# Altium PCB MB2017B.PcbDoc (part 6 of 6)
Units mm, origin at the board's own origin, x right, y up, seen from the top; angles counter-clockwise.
Board outline 148.19 x 169.19 mm, 4 copper layers (Top Layer, Mid Layer 1, Mid Layer 2, Bottom Layer), stack 1.498 mm thick; 458 components, 208 nets, 1223 pads, 6162 vias.
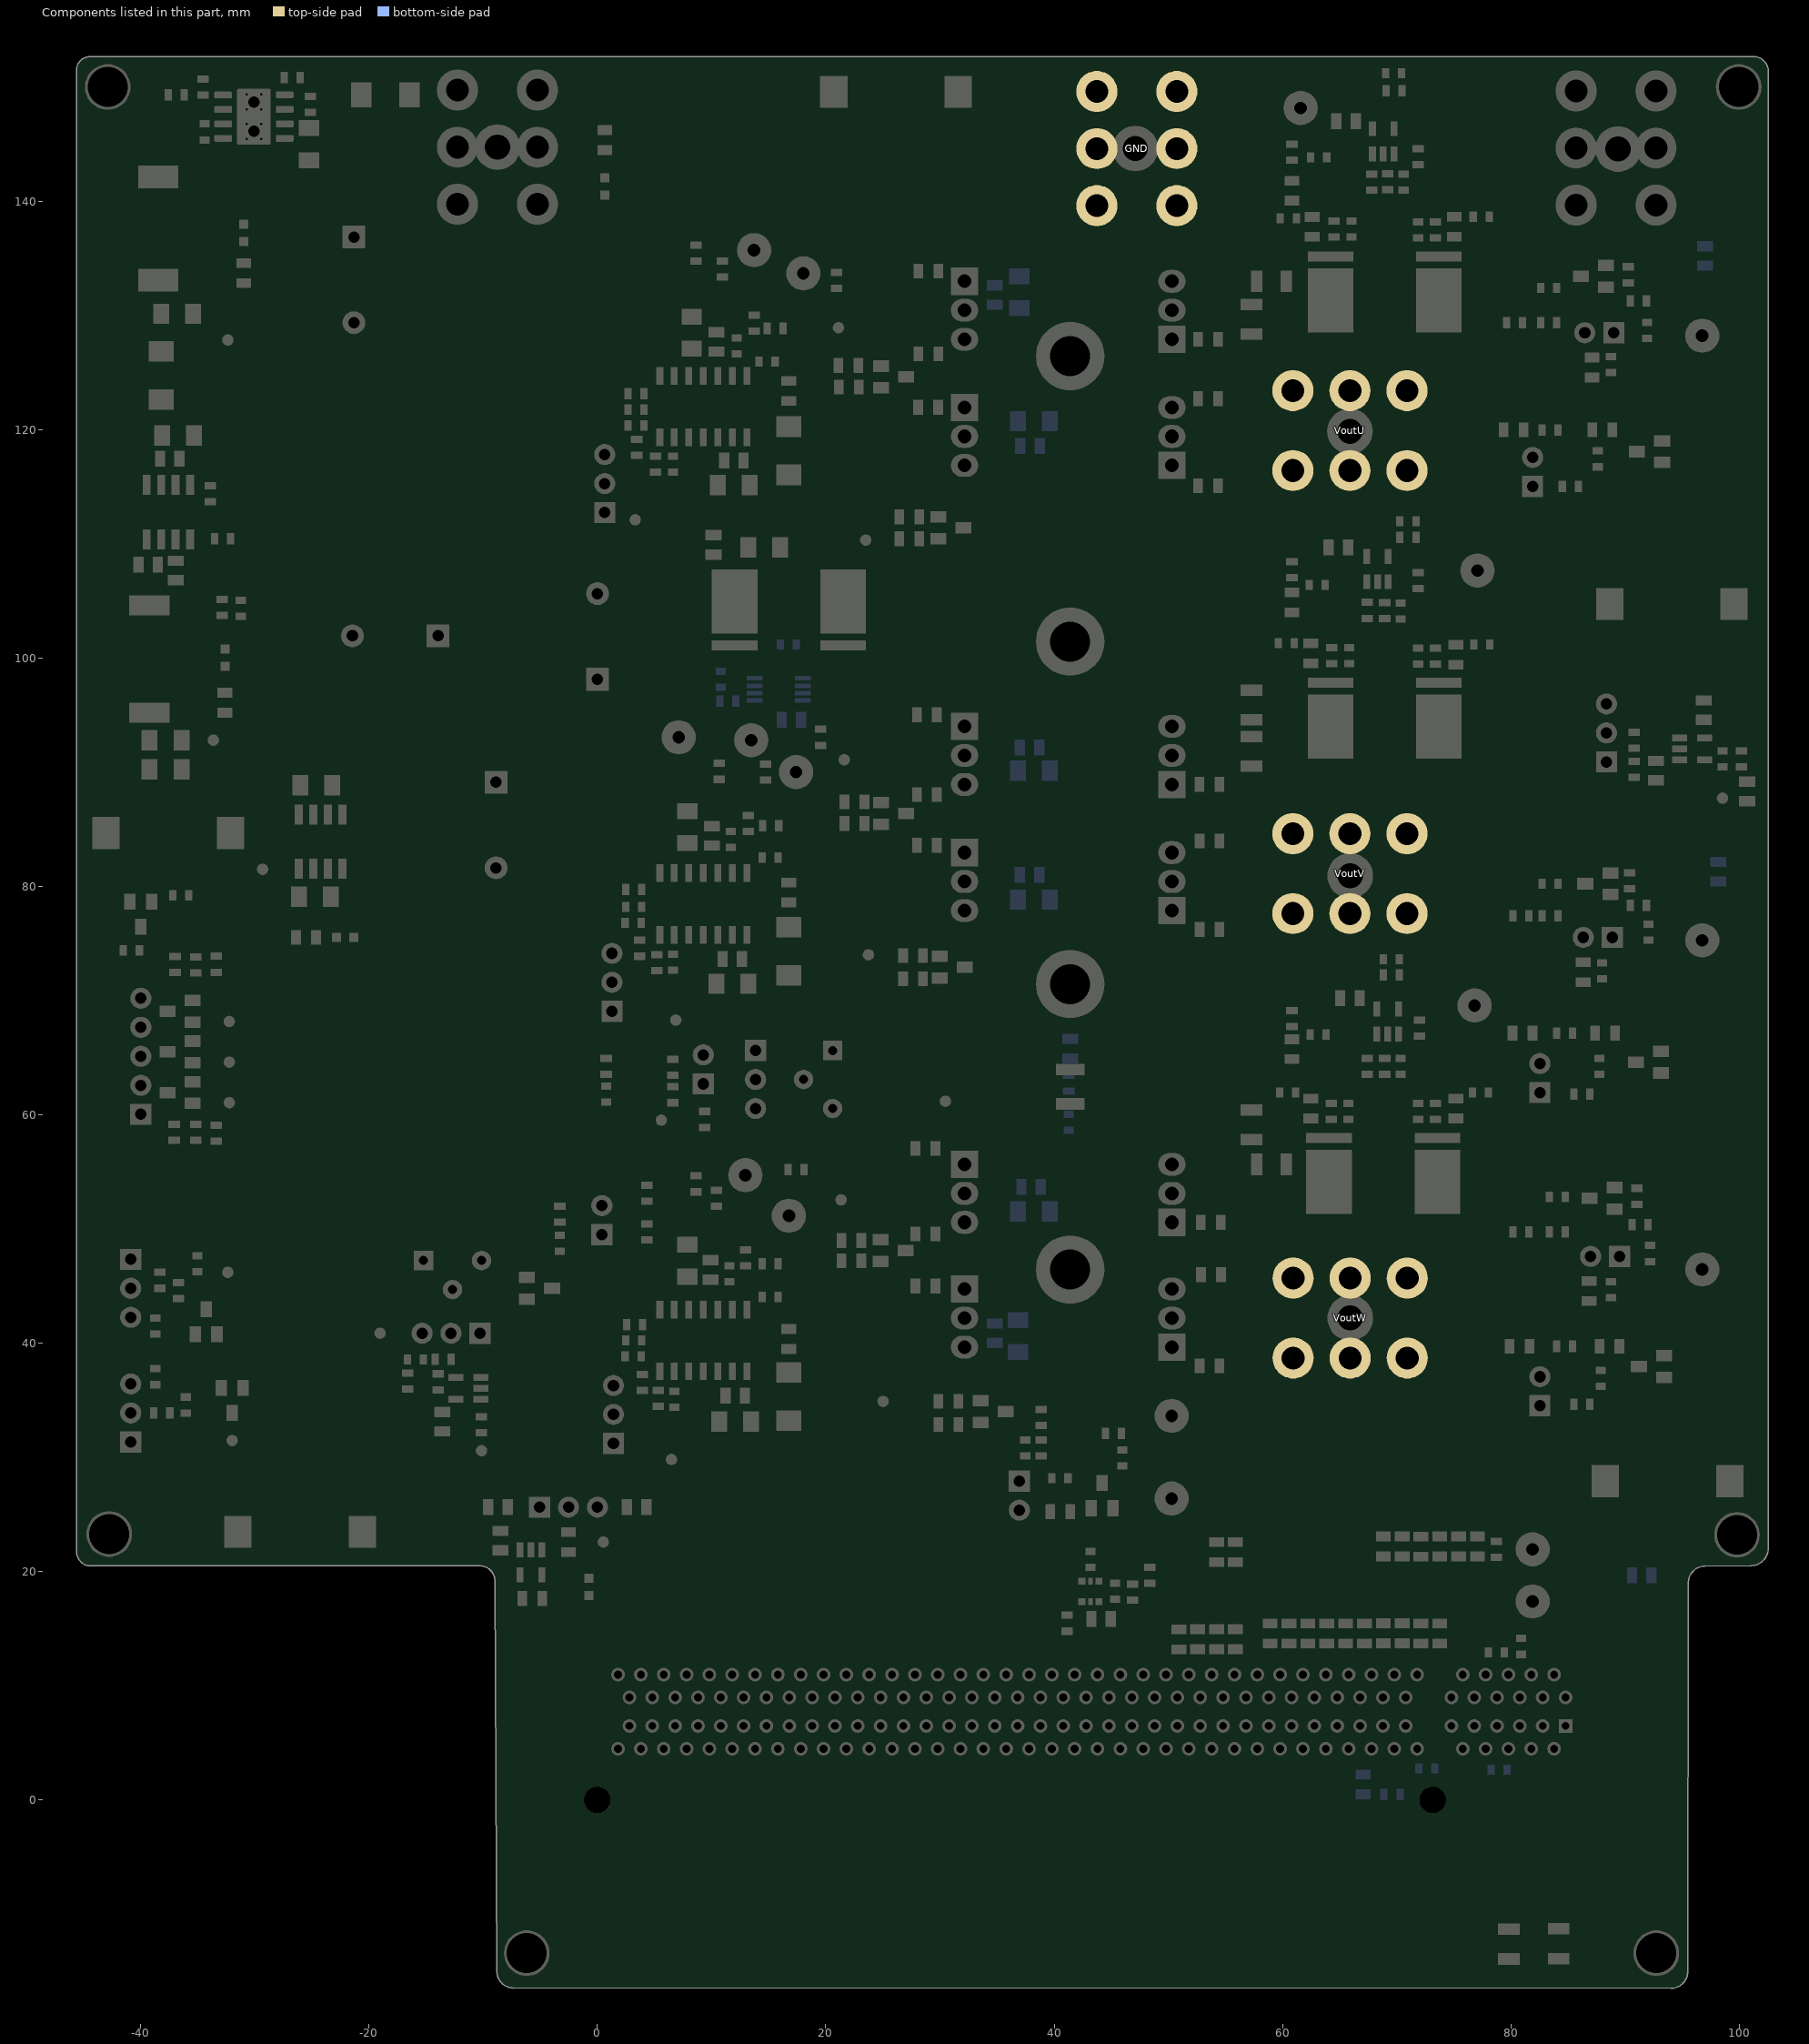
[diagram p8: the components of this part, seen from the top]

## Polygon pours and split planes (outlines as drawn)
GND on Mid Layer 1 "GND_L02_P015" (solid, remove dead copper, pour order 15): -44.577,152.4 100.838,152.4 102.108,151.13 102.108,21.844 101.219,20.955 96.012,20.955 95.123,20.066 95.123,-14.986 94.107,-16.002 -7.366,-16.002 -8.509,-14.859 -8.509,19.939 -9.525,20.955 -44.45,20.955 -45.339,21.844 -45.339,151.638
VoutW on Mid Layer 1 "VOUTW_L02_P002" (solid, pour order 2): 31.954,51.59 34.621,51.59 37.161,54.13 50.369,54.13 50.369,52.225 48.591,52.225 48.591,43.081 50.496,43.081 50.496,41.176 37.542,41.176 35.002,38.636 31.827,38.636 31.827,40.541 34.113,40.541 34.113,49.812 31.954,49.812
VoutU on Mid Layer 1 "VOUTU_L02_P000" (solid, pour order 0): 32.004,128.905 34.671,128.905 37.211,131.445 50.419,131.445 50.419,129.54 48.641,129.54 48.641,120.396 50.546,120.396 50.546,118.491 37.592,118.491 35.052,115.951 31.877,115.951 31.877,117.856 34.163,117.856 34.163,127.127 32.004,127.127
VoutV on Mid Layer 1 "VOUTV_L02_P001" (solid, pour order 1): 31.954,89.944 34.621,89.944 37.161,92.484 50.369,92.484 50.369,90.579 48.591,90.579 48.591,81.435 50.496,81.435 50.496,79.53 37.542,79.53 35.002,76.99 31.827,76.99 31.827,78.895 34.113,78.895 34.113,88.166 31.954,88.166
GND on Mid Layer 2 "GND_L03_P016" (solid, remove dead copper, pour order 16): -44.605,152.407 100.81,152.407 102.08,151.137 102.08,21.851 101.191,20.962 95.984,20.962 95.095,20.073 95.095,-14.979 94.079,-15.995 -7.394,-15.995 -8.537,-14.852 -8.537,19.946 -9.553,20.962 -44.478,20.962 -45.367,21.851 -45.367,151.645
VoutW on Mid Layer 2 "VOUTW_L03_P006" (solid, pour order 6): 32.004,51.562 34.671,51.562 37.211,54.102 50.419,54.102 50.419,52.197 48.641,52.197 48.641,43.053 50.546,43.053 50.546,41.148 37.592,41.148 35.052,38.608 31.877,38.608 31.877,40.513 34.163,40.513 34.163,49.784 32.004,49.784
VoutU on Mid Layer 2 "VOUTU_L03_P003" (solid, pour order 3): 32.004,128.905 34.671,128.905 37.211,131.445 50.419,131.445 50.419,129.54 48.641,129.54 48.641,120.396 50.546,120.396 50.546,118.491 37.592,118.491 35.052,115.951 31.877,115.951 31.877,117.856 34.163,117.856 34.163,127.127 32.004,127.127
VoutV on Mid Layer 2 "VOUTV_L03_P005" (solid, pour order 5): 32.004,89.916 34.671,89.916 37.211,92.456 50.419,92.456 50.419,90.551 48.641,90.551 48.641,81.407 50.546,81.407 50.546,79.502 37.592,79.502 35.052,76.962 31.877,76.962 31.877,78.867 34.163,78.867 34.163,88.138 32.004,88.138
GND on Bottom Layer "GND_L04_P017" (solid, remove dead copper, pour order 17): -44.577,152.4 100.838,152.4 102.108,151.13 102.108,21.844 101.219,20.955 96.012,20.955 95.123,20.066 95.123,-14.986 94.107,-16.002 -7.366,-16.002 -8.509,-14.859 -8.509,19.939 -9.525,20.955 -44.45,20.955 -45.339,21.844 -45.339,151.638
GND on Top Layer "GND_L01_P014" (solid, remove dead copper, pour order 14): -44.577,152.4 100.838,152.4 102.108,151.13 102.108,21.844 101.219,20.955 96.012,20.955 95.123,20.066 95.123,-14.986 94.107,-16.002 -7.366,-16.002 -8.509,-14.859 -8.509,19.939 -9.525,20.955 -44.45,20.955 -45.339,21.844 -45.339,151.638

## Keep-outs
Keep-Out Layer:
  circle w0.254: c-0.002,0 r1.351
  circle w0.254: c73.15,0 r1.351
  lines w0.3: 0.053,-13.927 0.053,-11.514 9.07,-11.514 9.07,-13.927 0.053,-13.927

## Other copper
Top Layer:
  rectangle net GND: 71.247,127.889 76.454,134.112
  rectangle net GND: 70.866,90.551 76.073,96.774
  rectangle net GND: 70.866,50.8 76.073,57.023
  region net VoutW: 72.931,36.235 72.931,47.665 58.961,47.665 58.961,36.235
  region net VoutV: 72.931,75.478 72.931,86.908 58.961,86.908 58.961,75.478
  region net VoutU: 72.898,114.173 72.898,125.603 58.928,125.603 58.928,114.173
  rectangle net GND: 70.612,129.921 77.851,132.715
  rectangle net GND: 70.739,92.583 77.978,95.377
  rectangle net GND: 70.231,52.705 77.47,55.499
  rectangle net OC_Bias: 6.477,73.914 6.985,76.073
  rectangle net NetQ18_1: 28.321,73.533 30.48,74.422
  rectangle net NetQ10_1: 22.987,48.641 25.146,49.403
  rectangle net NetC64_2: 3.683,40.005 4.064,41.783
  rectangle net OC_Bias: 6.477,35.814 6.985,37.592
  rectangle net OC_Bias: 6.477,117.475 6.985,119.507
  rectangle net GND: 43.688,17.018 45.72,17.653
  rectangle net W: 55.731,56.17 58.271,58.456
  rectangle net U: 55.753,130.429 58.293,132.715
  rectangle net V: 52.451,92.583 58.293,95.123
  rectangle net NetJ2_1: 55.722,96.647 58.262,128.905
  rectangle net NetJ3_2: 55.753,59.944 58.293,91.059
  rectangle net Vcc_power: 20.447,102.362 34.671,107.95
  rectangle net Vbat: 9.398,107.569 13.97,109.601
  rectangle net Vbat: 2.794,102.362 13.97,107.95
  rectangle net Vbat: 0.762,96.012 8.255,103.251
  rectangle net Vbat: -15.367,87.884 1.397,103.251
  rectangle net NetC2_1: -21.59,135.89 -20.32,150.368
  rectangle net NetC1_1: -34.671,144.907 -32.131,145.796
  rectangle net GND: 83.477,137.604 94.907,152.019
  rectangle net GND: 41.402,137.287 52.832,151.765
  rectangle net Vbat: -14.478,100.711 -3.048,151.765
  region net NetJ1_1: 59.817,56.642 66.167,56.642 66.167,51.181 62.103,51.181 62.103,54.737 59.817,54.737
  region net V: 56.388,95.123 59.944,95.123 59.944,96.647 66.167,96.647 66.167,91.059 59.944,91.059 59.944,92.583 56.388,92.583
  region net NetJ4_1: 59.817,133.985 66.294,133.985 66.294,128.397 62.23,128.397 62.23,132.08 59.817,132.08
  region net W: 45.466,56.696 45.466,43.688 50.641,43.688 50.641,45.72 48.609,45.72 48.609,54.737 58.261,54.737 58.261,56.696
  region net V: 45.466,94.996 45.466,82.042 50.673,82.042 50.673,83.947 48.641,83.947 48.641,93.091 58.293,93.091 58.293,94.996
  region net U: 45.466,133.985 45.466,121.031 50.673,121.031 50.673,122.936 48.641,122.936 48.641,132.08 58.293,132.08 58.293,133.985
  region net Vcc_power: 35.231,107.182 31.421,107.182 35.231,110.992
  region net Vcc_power: 34.677,103.684 34.677,99.874 30.867,103.684
  region net Vbat: 6.679,103.003 10.489,103.003 6.679,99.193
  region net Vcc_power: 31.75,131.445 37.465,131.445 37.465,41.275 31.877,41.275 31.877,43.18 34.163,43.18 34.163,52.197 31.877,52.197 31.877,54.102 32.004,53.975 34.163,53.975 34.163,79.502 31.877,79.502 31.877,81.407 34.163,81.407 34.163,90.551 31.877,90.551 31.877,92.456 34.163,92.456 34.163,118.491 31.877,118.491 31.877,120.396 34.163,120.396 34.163,129.54 31.75,129.54
  region net Vbat: 3.81,102.616 0,102.616 3.81,106.426
  region net Vbat: -3.81,102.362 -3.81,106.172 0,102.362
  region net Vbat: 1.143,96.139 4.953,96.139 1.143,92.329
  text "1" at 0.942,-13.292 h1.8
Mid Layer 1:
  rectangle net GND: 83.312,137.541 95.377,151.892
  rectangle net GND: 41.402,137.414 53.467,151.765
  rectangle net Epad: -33.147,144.78 -26.797,150.114
  rectangle net VoutU: 57.476,117.324 59.381,121.896
  rectangle net VoutV: 57.531,78.232 59.436,82.804
  rectangle net VoutW: 57.785,39.878 59.69,44.45
  rectangle net VoutW: 50.291,41.322 60.324,43.227
  rectangle net VoutV: 50.418,79.549 60.451,81.454
  rectangle net VoutU: 50.038,118.491 60.071,120.396
  region net VoutW: 73.082,36.514 73.082,47.944 59.112,47.944 59.112,36.514
  region net VoutV: 72.955,75.249 72.955,86.679 58.985,86.679 58.985,75.249
  region net VoutU: 72.898,114.046 72.898,125.476 58.928,125.476 58.928,114.046
  rectangle net VoutU: 31.695,127.13 34.285,128.936
  rectangle net VoutU: 47.117,129.67 49.708,131.476
  rectangle net VoutU: 48.21,118.618 50.8,120.424
  rectangle net VoutU: 32.081,115.951 34.671,117.757
  rectangle net VoutV: 47.956,90.678 50.546,92.484
  rectangle net VoutV: 31.695,88.141 34.285,89.947
  rectangle net VoutV: 31.696,77.105 34.287,78.911
  rectangle net VoutV: 48.135,79.658 50.726,81.464
  rectangle net VoutW: 48.337,52.197 50.927,54.003
  rectangle net VoutW: 48.337,41.275 50.927,43.081
  rectangle net VoutW: 31.695,38.608 34.285,40.671
  rectangle net VoutW: 31.954,49.784 34.544,51.59
  text "2" at 3.228,-13.292 h1.8
Mid Layer 2:
  rectangle net GND: 83.058,137.541 95.123,151.892
  rectangle net GND: 41.656,137.414 53.721,151.765
  rectangle net Epad: -33.147,144.78 -26.797,150.114
  rectangle net VoutU: 57.476,117.324 59.381,121.896
  rectangle net VoutW: 57.73,39.854 59.635,44.426
  rectangle net VoutV: 57.531,78.232 59.436,82.804
  rectangle net VoutV: 50.204,79.608 60.237,81.513
  rectangle net VoutW: 49.657,41.275 59.69,43.18
  rectangle net VoutU: 49.911,118.491 59.944,120.396
  region net VoutV: 72.967,75.303 72.967,86.733 58.997,86.733 58.997,75.303
  region net VoutU: 72.84,114.038 72.84,125.468 58.87,125.468 58.87,114.038
  region net VoutW: 73.025,36.449 73.025,47.879 59.055,47.879 59.055,36.449
  rectangle net VoutW: 31.877,49.629 34.467,51.435
  rectangle net VoutW: 31.75,38.608 34.34,40.64
  rectangle net VoutW: 47.625,41.247 50.215,43.053
  rectangle net VoutW: 48.006,52.169 50.596,53.975
  rectangle net VoutV: 32.004,77.061 34.594,78.867
  rectangle net VoutV: 48.006,79.601 50.596,81.407
  rectangle net VoutV: 48.006,90.65 50.596,92.456
  rectangle net VoutV: 32.258,88.11 34.848,89.916
  rectangle net VoutU: 31.623,127.099 34.213,128.905
  rectangle net VoutU: 48.006,129.639 50.596,131.445
  rectangle net VoutU: 48.006,118.59 50.596,120.396
  rectangle net VoutU: 32.131,115.923 34.721,117.729
  text "3" at 5.387,-13.271 h1.8
Bottom Layer:
  region net VoutW: 72.931,36.616 72.931,48.046 58.961,48.046 58.961,36.616
  region net VoutV: 72.931,75.478 72.931,86.908 58.961,86.908 58.961,75.478
  region net VoutU: 72.898,113.919 72.898,125.349 58.928,125.349 58.928,113.919
  rectangle net GND: 38.862,50.8 42.291,54.483
  rectangle net GND: 38.862,77.978 42.418,81.788
  rectangle net GND: 38.862,90.043 42.164,92.964
  rectangle net GND: 38.862,117.856 42.037,121.285
  rectangle net W: 55.731,56.17 58.271,58.456
  rectangle net NetJ3_2: 55.753,59.944 58.293,91.059
  rectangle net V: 52.451,92.583 58.293,95.123
  rectangle net NetJ2_1: 55.753,96.647 58.293,128.905
  rectangle net U: 55.753,130.429 58.293,132.715
  rectangle net Vcc_power: 19.558,102.362 35.052,107.95
  rectangle net Epad: -33.147,144.78 -26.797,150.114
  rectangle net Vbat: 2.794,102.362 13.97,107.95
  rectangle net Vbat: 0.762,96.012 8.255,103.251
  rectangle net Vbat: -15.367,87.884 1.397,103.251
  rectangle net GND: 83.433,137.558 94.863,152.019
  rectangle net GND: 41.275,137.668 53.34,152.019
  rectangle net Vbat: -14.478,100.33 -3.048,151.892
  region net W: 45.339,56.642 45.339,43.688 50.673,43.688 50.673,45.72 48.641,45.72 48.641,54.737 58.293,54.737 58.293,56.642
  region net V: 45.466,94.996 45.466,82.042 50.673,82.042 50.673,83.947 48.641,83.947 48.641,93.091 58.293,93.091 58.293,94.996
  region net U: 45.466,133.985 45.466,121.031 50.673,121.031 50.673,122.936 48.641,122.936 48.641,132.08 58.293,132.08 58.293,133.985
  region net Vcc_power: 35.061,107.064 35.061,110.874 31.251,107.064
  region net Vcc_power: 34.922,103.387 31.112,103.387 34.922,99.577
  region net Vbat: 7.484,103.883 7.484,100.073 11.294,103.883
  region net Vcc_power: 31.75,131.445 37.465,131.445 37.465,41.275 31.877,41.275 31.877,43.18 34.163,43.18 34.163,52.197 31.877,52.197 31.877,54.102 32.004,53.975 34.163,53.975 34.163,79.502 31.877,79.502 31.877,81.407 34.163,81.407 34.163,90.551 31.877,90.551 31.877,92.456 34.163,92.456 34.163,118.491 31.877,118.491 31.877,120.396 34.163,120.396 34.163,129.54 31.75,129.54
  region net Vbat: -3.683,102.235 0.127,102.235 -3.683,106.045
  region net Vbat: 3.81,102.616 3.81,106.426 0,102.616
  region net Vbat: 1.143,96.139 4.953,96.139 1.143,92.329
  text "4" at 7.673,-13.292 h1.8

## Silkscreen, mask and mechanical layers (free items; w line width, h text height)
Top Overlay:
  region: -22.923,45.466 -22.923,46.863 -25.146,46.863 -25.146,45.466
  region: -20.756,49.503 -20.756,50.9 -22.978,50.9 -22.978,49.503
  rectangle: -10.441,54.919 -9.044,57.141
  rectangle: -14.478,57.086 -13.081,59.309
  lines w0.2: -25.201,49.503 -25.201,50.9 -20.756,50.9 -20.756,49.503 -25.201,49.503 ; -25.146,45.466 -25.146,46.863 -20.701,46.863 -20.701,45.466 -25.146,45.466 ; -14.478,54.864 -13.081,54.864 -13.081,59.309 -14.478,59.309 -14.478,54.864 ; -10.441,54.919 -9.044,54.919 -9.044,59.364 -10.441,59.364 -10.441,54.919
  lines w0.25: -43.942,36.83 -43.942,36.322 -42.672,36.322 ; -43.942,41.402 -43.942,42.164 -42.672,42.164 ; -43.815,33.147 -43.815,33.909 -42.672,33.909 ; -43.815,45.466 -43.815,44.831 -42.799,44.831 ; -6.985,27.813 -5.08,27.813 -5.08,27.305 ; 0,27.305 0,27.813 1.905,27.813 ; 7.112,58.42 -8.255,58.42 -8.255,54.483 -8.255,53.721 -18.415,53.721 -18.415,66.548 4.953,66.548 4.953,67.31 12.954,67.31 12.954,69.85 26.035,69.85 26.035,57.785 15.24,57.785 15.24,58.42 10.541,58.42 ; 79.248,62.484 79.248,59.817 94.615,59.817 94.615,69.85 79.375,69.85 79.375,64.262 ; -29.718,29.21 -29.718,54.483 -19.05,54.483 -19.05,52.959 -6.985,52.959 -6.985,57.15 5.842,57.15 5.842,44.831 -2.54,44.831 -2.54,38.481 -7.366,38.481 -7.366,29.21 -29.718,29.21 ; 78.105,113.03 78.105,122.555 95.25,122.555 95.25,113.03 78.105,113.03 ; 79.121,32.385 94.615,32.385 94.615,42.037 79.121,42.037 79.121,32.385 ; 80.137,84.709 80.137,99.568 101.854,99.568 101.854,84.709 80.137,84.709
  lines w0.3: 2.286,-13.97 2.286,-11.557 0,-11.557 ; 4.699,-13.97 4.699,-11.557 ; 6.985,-13.97 6.985,-11.557 ; 0,-11.557 0,-13.97 9.017,-13.97 9.017,-11.557 0,-11.557
  text "Battery :  / 18V to 48V" at -2.232,147.505 h1.8
  text "GND" at 24.511,146.833 h1.8
  text "C" at -16.002,119.377 h7
  text "H" at -23.368,118.863 h10
  text "I" at -29.718,118.085 h10
  text "OCuU / disable" at -6.35,116.078 h1.8
  text "ENGINEERING / SAMPLE" at -23.685,113.582 h1.8
  text "VoutU 6S Meas." at 82.931,111.4 h1.8
  text "OCuU / enable" at -6.35,110.998 h1.8
  text "JP2, JP10 : / Not fitted <= 24V / Fitted       <= 48V" at 101.051,110.458 h1.8 r90
  text "GND" at 92.583,106.574 h1.8
  text "Ref. 6S" at 81.153,95.398 h1.8
  text "Ref. PCI" at 80.518,90.19 h1.8
  text "GND" at -39.243,86.889 h1.8
  text "OCuV / disable" at -5.969,72.898 h1.8
  text "Hall Sensors" at -43.836,71.628 h1.8 r90
  text "+5V" at -44.706,69.871 h1.8
  text "OCuV / enable" at -5.969,67.437 h1.8
  text "H1" at -43.817,67.31 h1.8
  text "K" at -27.813,66.146 h12
  text "H2" at -43.817,64.77 h1.8
  text "H3" at -43.817,61.997 h1.8
  text "Overcurrent JP9 / Not fitted = 152A / Fitted       = 236A" at -18.034,61.595 h1.8
  text "GND" at -45.087,59.457 h1.8
  text "E" at -27.425,58.83 h10
  text "JP3, JP13 : / Not fitted <= 24V / Fitted       <= 48V" at 100.766,58.012 h1.8 r90
  text "VoutV 6S Meas." at 81.534,57.933 h1.8
  text "OCu var." at -11.176,53.73 h1.8 r90
  text "JP8 :  / OCu fixed" at -15.24,53.608 h1.8 r90
  text "GND" at -40.407,51.562 h1.8 r90
  text "JP11 :  / Ov fixed" at -26.656,51.435 h1.8
  text "Ov var." at -26.407,47.371 h1.8
  text "Brake" at -43.326,45.847 h1.8 r90
  text "+3V3" at -43.328,37.211 h1.8 r90
  text "OCuW / disable" at -6.223,35.433 h1.8
  text "VoutW 6S Meas." at 80.264,30.628 h1.8
  text "JP4, JP15 : / Not fitted <= 24V / Fitted       <= 48V" at 100.965,29.972 h1.8 r90
  text "OCuW / enable" at -6.096,29.914 h1.8
  text "Overvoltage JP12 / Not fitted : 24V, Ov = 48.5V / Fitted : 48V, Ov = 94.4V" at -21.717,29.702 h1.8 r90
  text "3V3 Power" at -15.24,27.326 h1.8
  text "3V3 PCI" at 2.286,27.326 h1.8
  text "Throttle" at -43.326,26.797 h1.8 r90
  text "GND" at -27.94,25.675 h1.8
  text "GND" at -40.407,25.4 h1.8 r90
  text "GND" at 92.456,25.04 h1.8
  text "JP16 : / Not fitted <= 24V / Fitted       <= 48V" at 19.907,22.774 h1.8
  text "Not For / Commercial Use" at 14.287,-15.335 h1.8
  text "Low Voltage High Current / Motor Driver" at 37.941,-15.918 h2.5
Bottom Overlay:
  lines w0.3: 2.286,-13.97 2.286,-11.557 ; 4.699,-13.97 4.699,-11.557 ; 6.985,-13.97 6.985,-11.557 ; 0,-13.97 0,-11.557 9.017,-11.557 9.017,-13.97 0,-13.97
  text "ETR" at 68.072,1.651 h1.8
M1-Board Shape:
  lines w0.25: -45.631,21.762 -45.631,151.544 ; -44.481,152.694 101.167,152.709 ; -44.377,20.508 -44.362,20.524 -10.318,20.524 ; -8.988,19.195 -8.814,-14.986 ; -7.339,-16.457 94.04,-16.48 ; 95.502,-15.018 95.553,19.022 ; 97.026,20.496 101.012,20.532 ; 102.563,22.083 102.564,151.41
  lines w0.254: -45.631,21.762 ccw(c-44.377,21.762) -44.377,20.508 ; -45.631,151.544 cw(c-44.481,151.544) -44.481,152.694 ; -10.318,20.524 cw(c-10.318,19.195) -8.988,19.195 ; -8.814,-14.986 ccw(c-7.339,-14.986) -7.339,-16.46 ; 94.04,-16.48 ccw(c94.04,-15.018) 95.502,-15.018 ; 95.553,19.022 cw(c97.026,19.022) 97.026,20.496 ; 101.012,20.532 ccw(c101.012,22.083) 102.563,22.083 ; 101.265,152.709 cw(c101.265,151.41) 102.564,151.41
